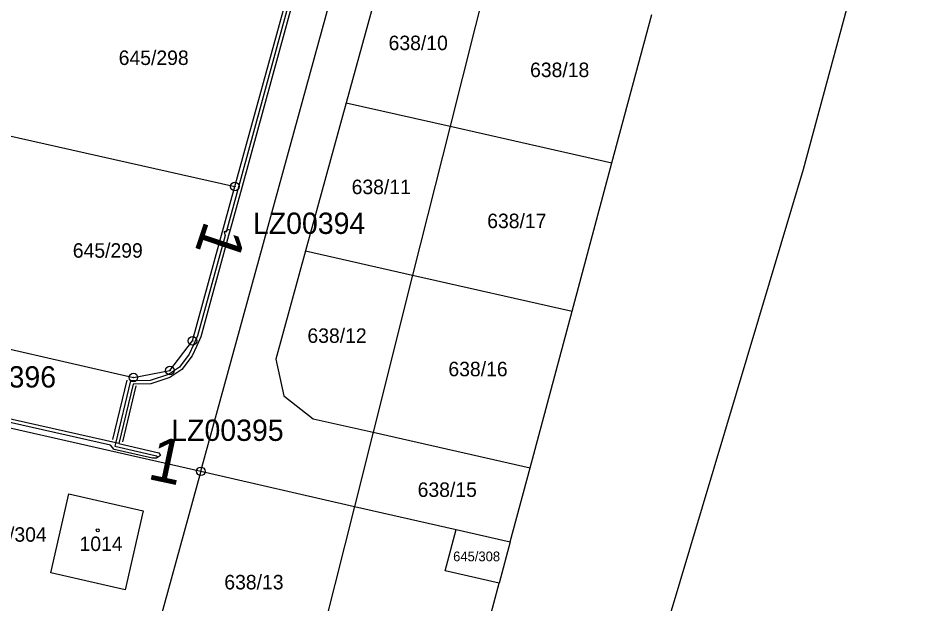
# Model space of a CAD drawing. Extents: x -738131 to -734179, y -1033447 to -1030078.
# Drawn here: x -735741.5 to -735634.9, y -1033013.9 to -1032945.2 of the extents above; entities that cross this region are included whole.
import ezdxf

# ---------------------------------------------------------------- set-up
doc = ezdxf.new("R2010")
doc.units = 0
for name, color, linetype in [('ftf_2010', 7, 'Continuous'), ('ftf_2140', 7, 'Continuous'), ('ftf_3010', 7, 'Continuous'), ('ftf_3010_ftf_3010_gtda_3015_gtda_3015_1', 7, 'Continuous'), ('ftf_3210', 7, 'Continuous'), ('Vrstva 1', 7, 'Continuous'), ('Vrstva 2', 7, 'Continuous'), ('Vrstva 5', 7, 'Continuous'), ('Vrstva 8', 7, 'Continuous')]:
    doc.layers.add(name, color=color, linetype=linetype)

msp = doc.modelspace()

# ---------------------------------------------------------------- linework, layer by layer
at = {"layer": 'ftf_2010'}
for points in [[(-735709.43, -1032941.7), (-735709.42, -1032942.11), (-735709.5, -1032942.41), (-735709.64, -1032943.11), (-735715.59, -1032964.82), (-735717.09, -1032970.28), (-735717.3, -1032970.22)], [(-735717.3, -1032970.22), (-735717.2, -1032970.66), (-735720.43, -1032982.42), (-735720.92, -1032983.5), (-735721.41, -1032984.59), (-735722.57, -1032986.1), (-735723.86, -1032986.98), (-735726.01, -1032987.67), (-735728.33, -1032987.72), (-735730.09, -1032995.06), (-735730.16, -1032995.37), (-735725.25, -1032996.5), (-735725.22, -1032996.55), (-735725.27, -1032996.78)], [(-735725.27, -1032996.78), (-735725.73, -1032996.8), (-735730.24, -1032995.76), (-735730.68, -1032995.25), (-735743.89, -1032992.29), (-735744.39, -1032992.22), (-735745.35, -1032992.02), (-735745.83, -1032991.88), (-735751.73, -1032990.54), (-735751.78, -1032990.77)]]:
    msp.add_lwpolyline(points, dxfattribs=at)
at = {"layer": 'ftf_2140'}
for points in [[(-735708.84, -1032941.44), (-735709.02, -1032942.16), (-735709.11, -1032942.5), (-735709.25, -1032943.2), (-735715.21, -1032964.92), (-735716.6, -1032970)], [(-735716.6, -1032970), (-735716.79, -1032970.67), (-735720.05, -1032982.56), (-735720.56, -1032983.67), (-735721.07, -1032984.79), (-735722.29, -1032986.4), (-735723.69, -1032987.34), (-735725.94, -1032988.06), (-735728.01, -1032988.11), (-735729.68, -1032995.07), (-735724.98, -1032996.15), (-735724.8, -1032996.48), (-735725.27, -1032996.78)], [(-735717.3, -1032970.22), (-735716.81, -1032969.94), (-735716.6, -1032970)], [(-735729.68, -1032995.06), (-735743.82, -1032991.9), (-735744.32, -1032991.82), (-735745.26, -1032991.63), (-735745.73, -1032991.5), (-735751.25, -1032990.24)]]:
    msp.add_lwpolyline(points, dxfattribs=at)
at = {"layer": 'ftf_3210'}
for points in [[(-735730.38, -1032994.58), (-735728.72, -1032987.63)], [(-735729.21, -1032994.86), (-735727.65, -1032988.3)]]:
    msp.add_lwpolyline(points, dxfattribs=at)
at = {"layer": 'Vrstva 1'}
for points in [[(-735649.28, -1032962.9), (-735634.93, -1032909.75)], [(-735720.05, -1032998.33), (-735701.24, -1032929.83)], [(-735698.21, -1032937.72), (-735702.99, -1032955.09)], [(-735686.39, -1032940.38), (-735690.79, -1032957.85)], [(-735716.06, -1032964.92), (-735709.78, -1032942.02)], [(-735671.79, -1032962.15), (-735667.12, -1032944.75)], [(-735702.99, -1032955.09), (-735707.76, -1032972.47)], [(-735702.99, -1032955.09), (-735690.79, -1032957.85)], [(-735690.79, -1032957.85), (-735695.19, -1032975.31)], [(-735690.79, -1032957.85), (-735671.79, -1032962.15)], [(-735746.2, -1032958.15), (-735716.06, -1032964.92)], [(-735676.46, -1032979.55), (-735671.79, -1032962.15)], [(-735670.39, -1033033.34), (-735649.28, -1032962.9)], [(-735721.03, -1032983.03), (-735716.06, -1032964.92)], [(-735707.76, -1032972.47), (-735711.24, -1032985.17)], [(-735707.76, -1032972.47), (-735695.19, -1032975.31)], [(-735695.19, -1032975.31), (-735699.83, -1032993.74)], [(-735695.19, -1032975.31), (-735676.46, -1032979.55)], [(-735681.38, -1032997.92), (-735676.46, -1032979.55)], [(-735751.54, -1032981.93), (-735727.98, -1032987.32)], [(-735723.69, -1032986.51), (-735721.03, -1032983.03)], [(-735711.24, -1032985.17), (-735710.33, -1032989.47)], [(-735727.98, -1032987.32), (-735723.69, -1032986.51)], [(-735710.33, -1032989.47), (-735706.85, -1032992.16)], [(-735744.92, -1032992.67), (-735720.05, -1032998.33)], [(-735706.85, -1032992.16), (-735699.83, -1032993.74)], [(-735699.83, -1032993.74), (-735702.03, -1033002.44)], [(-735699.83, -1032993.74), (-735681.38, -1032997.92)], [(-735720.05, -1032998.33), (-735726.34, -1033021.23)], [(-735720.05, -1032998.33), (-735702.03, -1033002.44)], [(-735683.72, -1033006.61), (-735681.38, -1032997.92)], [(-735737.67, -1033010.23), (-735735.56, -1033000.96)], [(-735735.56, -1033000.96), (-735726.84, -1033002.95)], [(-735702.03, -1033002.44), (-735707.77, -1033025.25)], [(-735702.03, -1033002.44), (-735690.06, -1033005.17)], [(-735726.84, -1033002.95), (-735728.95, -1033012.22)], [(-735691.35, -1033009.99), (-735690.06, -1033005.17)], [(-735690.06, -1033005.17), (-735683.72, -1033006.61)], [(-735683.72, -1033006.61), (-735685.01, -1033011.44)], [(-735685.01, -1033011.44), (-735691.35, -1033009.99)], [(-735728.95, -1033012.22), (-735737.67, -1033010.23)], [(-735689.76, -1033029.15), (-735685.01, -1033011.44)]]:
    msp.add_lwpolyline(points, dxfattribs=at)
at = {"layer": 'Vrstva 5'}
msp.add_circle((-735732.16, -1033005.25), 0.175, dxfattribs=at)
at = {"layer": 'Vrstva 8'}
for centre, radius in [((-735716.06, -1032964.92), 0.5), ((-735716.06, -1032964.92), 0.0303), ((-735721.03, -1032983.03), 0.5), ((-735721.03, -1032983.03), 0.0303), ((-735723.69, -1032986.51), 0.5), ((-735723.69, -1032986.51), 0.0303), ((-735727.98, -1032987.32), 0.5), ((-735727.98, -1032987.32), 0.0303), ((-735720.05, -1032998.33), 0.5), ((-735720.05, -1032998.33), 0.0303)]:
    msp.add_circle(centre, radius, dxfattribs=at)

# ---------------------------------------------------------------- texts
at = {"layer": 'ftf_3010'}
for rotation, p in [(251.552, (-735719.56, -1032968.78)), (348, (-735726.45, -1032999.19))]:
    msp.add_text('1', height=5.2, rotation=rotation, dxfattribs=at).set_placement(p)
at = {"layer": 'ftf_3010_ftf_3010_gtda_3015_gtda_3015_1'}
for s, p in [('LZ00394', (-735713.94, -1032970.48)), ('LZ00396', (-735750.25, -1032988.5)), ('LZ00395', (-735723.53, -1032994.76))]:
    msp.add_text(s, height=2.5, dxfattribs=at).set_placement(p)
at = {"layer": 'Vrstva 2'}
for s, height, p in [('638/10', 1.7, (-735698.01, -1032948.92)), ('645/298', 1.7, (-735729.7, -1032950.66)), ('638/18', 1.7, (-735681.4, -1032952.08)), ('638/11', 1.7, (-735702.35, -1032965.81)), ('638/17', 1.7, (-735686.43, -1032969.8)), ('645/299', 1.7, (-735735.09, -1032973.27)), ('638/12', 1.7, (-735707.54, -1032983.26)), ('638/16', 1.7, (-735690.99, -1032987.18)), ('638/15', 1.7, (-735694.6, -1033001.33)), ('645/304', 1.7, (-735746.37, -1033006.59)), ('1014', 1.7, (-735734.3, -1033007.68)), ('645/308', 1.14, (-735690.43, -1033008.88)), ('638/13', 1.7, (-735717.3, -1033012.18))]:
    msp.add_text(s, height=height, dxfattribs=at).set_placement(p)

doc.saveas('drawing.dxf')
